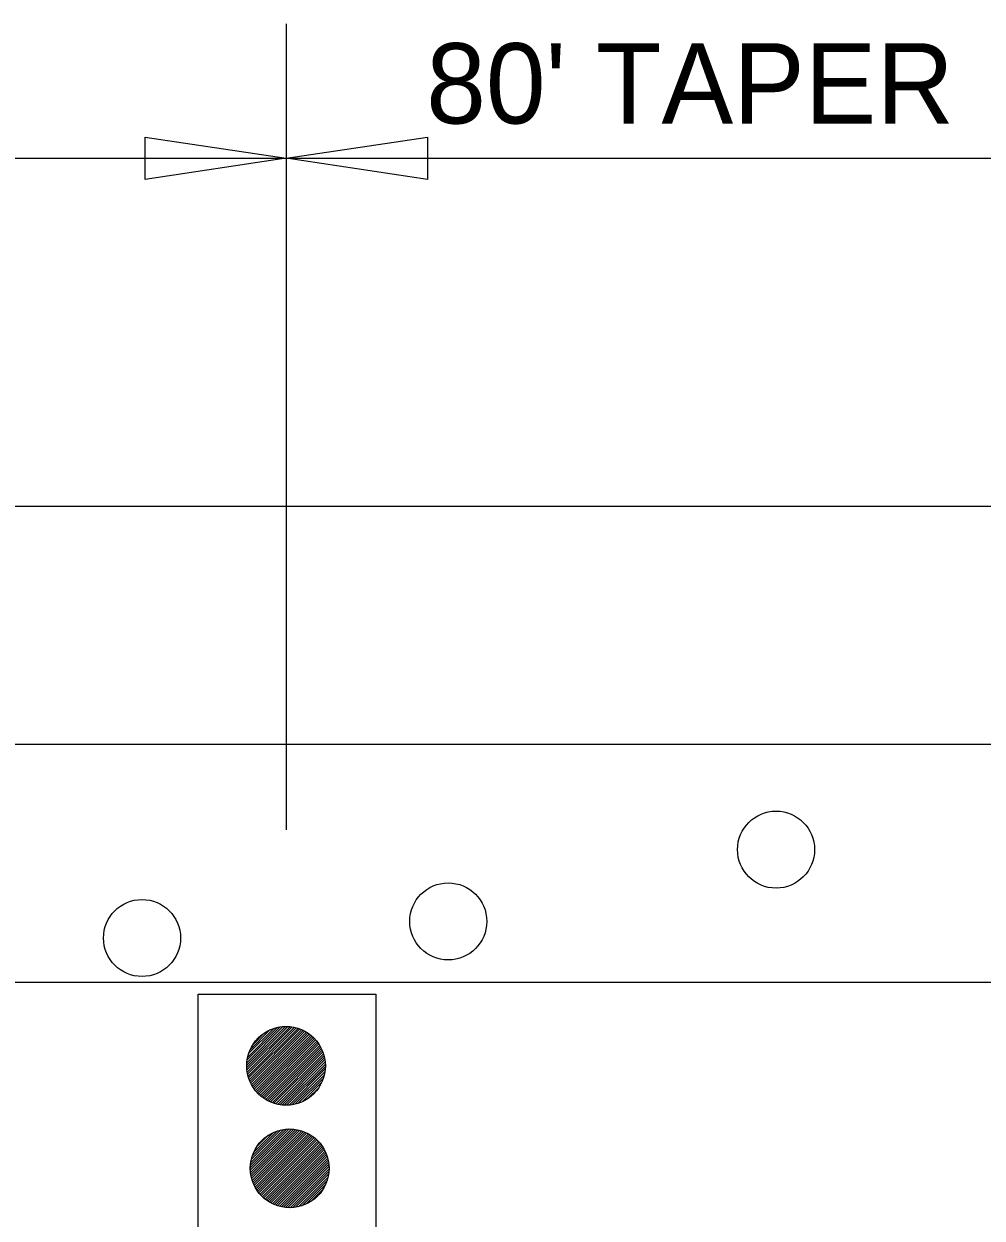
# Model space of a CAD drawing. Extents: x 1925873 to 1930787, y 596452 to 599617.
# Drawn here: x 1926240.2 to 1926311.8, y 597391.5 to 597480.7 of the extents above; entities that cross this region are included whole.
import ezdxf

# ---------------------------------------------------------------- set-up
doc = ezdxf.new("R2010")
doc.units = 0
doc.layers.add('Default', color=7, linetype='Continuous')

msp = doc.modelspace()

# ---------------------------------------------------------------- linework, layer by layer
at = {"layer": 'Default'}
for p, q in [((1926259.77, 597480.703), (1926259.77, 597420.473)), ((1926249.226, 597469.081), (1926249.226, 597472.247)), ((1926249.226, 597472.247), (1926259.77, 597470.664)), ((1926259.77, 597470.664), (1926270.313, 597472.247)), ((1926270.313, 597472.247), (1926270.313, 597469.081)), ((1926209.099, 597470.664), (1926259.77, 597470.664)), ((1926259.77, 597470.664), (1926249.226, 597469.081)), ((1926259.77, 597470.664), (1926333.705, 597470.664)), ((1926270.313, 597469.081), (1926259.77, 597470.664)), ((1925910.152, 597444.674), (1926778.093, 597444.674)), ((1925910.152, 597426.885), (1926778.093, 597426.885)), ((1925910.152, 597409.096), (1926778.093, 597409.096)), ((1926256.81, 597402.888), (1926259.709, 597405.787)), ((1926256.813, 597402.71), (1926259.887, 597405.784)), ((1926256.819, 597403.078), (1926259.519, 597405.778)), ((1926256.825, 597402.542), (1926260.055, 597405.772)), ((1926256.842, 597403.282), (1926259.315, 597405.755)), ((1926256.846, 597402.382), (1926260.215, 597405.751)), ((1926256.875, 597402.23), (1926260.368, 597405.722)), ((1926256.885, 597403.506), (1926259.092, 597405.713)), ((1926256.91, 597402.084), (1926260.513, 597405.687)), ((1926256.951, 597401.944), (1926260.653, 597405.646)), ((1926256.954, 597403.756), (1926258.841, 597405.643)), ((1926256.998, 597401.81), (1926260.787, 597405.599)), ((1926257.05, 597401.681), (1926260.916, 597405.547)), ((1926257.068, 597404.05), (1926258.547, 597405.53)), ((1926257.107, 597401.557), (1926261.04, 597405.49)), ((1926257.168, 597401.438), (1926261.159, 597405.429)), ((1926257.235, 597401.323), (1926261.274, 597405.363)), ((1926257.284, 597404.448), (1926258.149, 597405.313)), ((1926257.305, 597401.213), (1926261.385, 597405.292)), ((1926257.379, 597401.106), (1926261.491, 597405.218)), ((1926257.458, 597401.004), (1926261.593, 597405.139)), ((1926257.54, 597400.905), (1926261.692, 597405.057)), ((1926257.627, 597400.811), (1926261.786, 597404.97)), ((1926257.717, 597400.721), (1926261.877, 597404.88)), ((1926257.812, 597400.634), (1926261.963, 597404.785)), ((1926257.91, 597400.552), (1926262.046, 597404.687)), ((1926258.013, 597400.473), (1926262.124, 597404.585)), ((1926258.119, 597400.399), (1926262.199, 597404.478)), ((1926258.23, 597400.328), (1926262.269, 597404.368)), ((1926258.344, 597400.262), (1926262.335, 597404.253)), ((1926258.464, 597400.201), (1926262.396, 597404.133)), ((1926258.588, 597400.144), (1926262.453, 597404.009)), ((1926258.717, 597400.092), (1926262.505, 597403.88)), ((1926258.851, 597400.045), (1926262.552, 597403.746)), ((1926258.991, 597400.004), (1926262.593, 597403.607)), ((1926259.137, 597399.969), (1926262.628, 597403.461)), ((1926259.289, 597399.941), (1926262.657, 597403.308)), ((1926259.449, 597399.92), (1926262.677, 597403.148)), ((1926259.617, 597399.907), (1926262.69, 597402.98)), ((1926259.795, 597399.905), (1926262.693, 597402.802)), ((1926259.985, 597399.914), (1926262.684, 597402.612)), ((1926260.19, 597399.937), (1926262.66, 597402.408)), ((1926260.413, 597399.98), (1926262.618, 597402.184)), ((1926260.664, 597400.049), (1926262.548, 597401.934)), ((1926260.959, 597400.163), (1926262.434, 597401.638)), ((1926261.358, 597400.382), (1926262.216, 597401.239)), ((1926257.079, 597395.229), (1926259.978, 597398.128)), ((1926257.082, 597395.051), (1926260.156, 597398.125)), ((1926257.088, 597395.419), (1926259.788, 597398.119)), ((1926257.095, 597394.883), (1926260.325, 597398.113)), ((1926257.112, 597395.623), (1926259.584, 597398.096)), ((1926257.116, 597394.723), (1926260.484, 597398.092)), ((1926257.144, 597394.571), (1926260.637, 597398.063)), ((1926257.154, 597395.847), (1926259.361, 597398.053)), ((1926257.179, 597394.425), (1926260.783, 597398.028)), ((1926257.221, 597394.285), (1926260.922, 597397.987)), ((1926257.223, 597396.097), (1926259.111, 597397.984)), ((1926257.267, 597394.151), (1926261.056, 597397.94)), ((1926257.319, 597394.022), (1926261.185, 597397.888)), ((1926257.337, 597396.391), (1926258.816, 597397.87)), ((1926257.376, 597393.898), (1926261.309, 597397.831)), ((1926257.438, 597393.779), (1926261.429, 597397.77)), ((1926257.504, 597393.664), (1926261.544, 597397.704)), ((1926257.554, 597396.789), (1926258.419, 597397.654)), ((1926257.574, 597393.553), (1926261.654, 597397.633)), ((1926257.649, 597393.447), (1926261.761, 597397.559)), ((1926257.727, 597393.345), (1926261.863, 597397.48)), ((1926257.81, 597393.246), (1926261.961, 597397.398)), ((1926257.896, 597393.152), (1926262.056, 597397.311)), ((1926257.987, 597393.062), (1926262.146, 597397.221)), ((1926258.081, 597392.975), (1926262.232, 597397.126)), ((1926258.18, 597392.892), (1926262.315, 597397.028)), ((1926258.282, 597392.814), (1926262.393, 597396.926)), ((1926258.388, 597392.74), (1926262.468, 597396.819)), ((1926258.499, 597392.669), (1926262.538, 597396.709)), ((1926258.614, 597392.603), (1926262.604, 597396.594)), ((1926258.733, 597392.542), (1926262.666, 597396.474)), ((1926258.857, 597392.485), (1926262.723, 597396.35)), ((1926258.986, 597392.433), (1926262.775, 597396.221)), ((1926259.12, 597392.386), (1926262.821, 597396.087)), ((1926259.26, 597392.345), (1926262.862, 597395.947)), ((1926259.406, 597392.31), (1926262.897, 597395.802)), ((1926259.558, 597392.282), (1926262.926, 597395.649)), ((1926259.718, 597392.261), (1926262.947, 597395.489)), ((1926259.887, 597392.248), (1926262.959, 597395.321)), ((1926260.065, 597392.245), (1926262.962, 597395.143)), ((1926260.255, 597392.254), (1926262.953, 597394.953)), ((1926260.459, 597392.278), (1926262.93, 597394.748)), ((1926260.683, 597392.32), (1926262.887, 597394.525)), ((1926260.933, 597392.39), (1926262.817, 597394.274)), ((1926261.228, 597392.504), (1926262.703, 597393.979)), ((1926261.627, 597392.722), (1926262.485, 597393.58))]:
    msp.add_line(p, q, dxfattribs=at)
msp.add_lwpolyline([(1926253.176, 597408.199), (1926266.469, 597408.199), (1926266.469, 597383.664), (1926253.176, 597383.664)], close=True, dxfattribs=at)
for centre, radius in [((1926296.365, 597419.003), 2.878), ((1926271.869, 597413.637), 2.878), ((1926248.991, 597412.398), 2.878), ((1926259.751, 597402.846), 2.942), ((1926260.021, 597395.187), 2.942)]:
    msp.add_circle(centre, radius, dxfattribs=at)

# ---------------------------------------------------------------- texts
msp.add_text("80' TAPER", height=5.9996, rotation=360, dxfattribs=at).set_placement((1926270.222, 597473.259))

doc.saveas('drawing.dxf')
